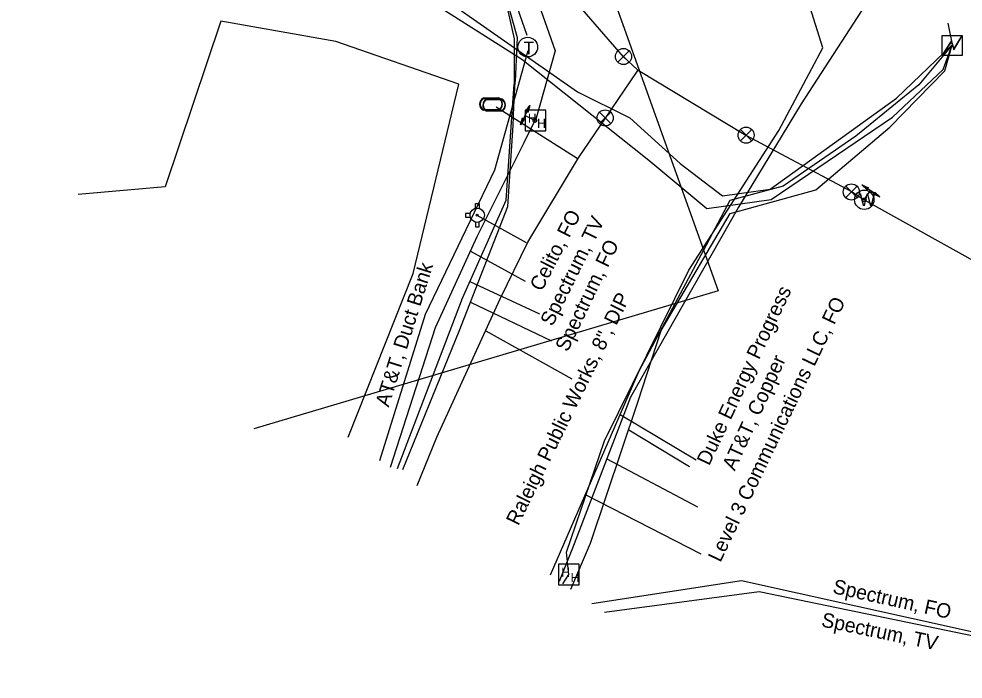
# Model space of a CAD drawing. Extents: x 2070721 to 2083340, y 729290 to 737883.
# Drawn here: x 2080186.1 to 2080447.3, y 733834.7 to 734017.2 of the extents above; entities that cross this region are included whole.
import ezdxf

# ---------------------------------------------------------------- set-up
doc = ezdxf.new("R2010")
doc.units = 0
for name, color, linetype in [('Exist Utilities Power Transformer CELL', 7, 'Continuous'), ('Exist Utilities Power UG Cable SUE LOS B', 7, 'Continuous'), ('Exist Utilities Power UG Cable SUE LOS B Leader', 7, 'Continuous'), ('Exist Utilities Power UG Cable SUE LOS B Text', 7, 'Continuous'), ('Exist Utilities Power UG Cable SUE LOS C', 7, 'Continuous'), ('Exist Utilities Telephone Change of Service SUE CELL', 7, 'Continuous'), ('Exist Utilities Telephone Hand Hole CELL', 7, 'Continuous'), ('Exist Utilities Telephone Manhole CELL', 7, 'Continuous'), ('Exist Utilities Telephone UG Cable SUE LOS C', 7, 'Continuous'), ('Exist Utilities Telephone UG Cable SUE LOS C Leader', 7, 'Continuous'), ('Exist Utilities Telephone UG Cable SUE LOS C Text', 7, 'Continuous'), ('Exist Utilities Telephone UG Conduit SUE LOS B', 7, 'Continuous'), ('Exist Utilities Telephone UG Conduit SUE LOS B Text', 7, 'Continuous'), ('Exist Utilities Telephone UG FO SUE LOS B', 7, 'Continuous'), ('Exist Utilities Telephone UG FO SUE LOS B Leader', 7, 'Continuous'), ('Exist Utilities Telephone UG FO SUE LOS B Text', 7, 'Continuous'), ('Exist Utilities Telephone UG FO SUE LOS C', 7, 'Continuous'), ('Exist Utilities Telephone UG FO SUE LOS C Leader', 7, 'Continuous'), ('Exist Utilities Telephone UG FO SUE LOS C Text', 7, 'Continuous'), ('Exist Utilities TV Hand Hole CELL', 7, 'Continuous'), ('Exist Utilities TV UG Cable SUE LOS C', 7, 'Continuous'), ('Exist Utilities TV UG Cable SUE LOS C Leader', 7, 'Continuous'), ('Exist Utilities TV UG Cable SUE LOS C Text', 7, 'Continuous'), ('Exist Utilities TV UG FO Cable SUE LOS C', 7, 'Continuous'), ('Exist Utilities TV UG FO Cable SUE LOS C Leader', 7, 'Continuous'), ('Exist Utilities TV UG FO Cable SUE LOS C Text', 7, 'Continuous'), ('Exist Utilities Water Change of Service SUE CELL', 7, 'Continuous'), ('Exist Utilities Water Fire Hydrant CELL', 7, 'Continuous'), ('Exist Utilities Water Manhole CELL', 7, 'Continuous'), ('Exist Utilities Water Meter CELL', 7, 'Continuous'), ('Exist Utilities Water UG Line SUE LOS B', 7, 'Continuous'), ('Exist Utilities Water UG Line SUE LOS B Leader', 7, 'Continuous'), ('Exist Utilities Water UG Line SUE LOS B Text', 7, 'Continuous'), ('Exist Utilities Water UG Line SUE LOS C', 7, 'Continuous'), ('Exist Utilities Water Valve CELL', 7, 'Continuous')]:
    doc.layers.add(name, color=color, linetype=linetype)

msp = doc.modelspace()

# ---------------------------------------------------------------- linework, layer by layer
at = {"layer": 'Exist Utilities Power Transformer CELL'}
msp.add_line((2080444.29, 734010.08), (2080444.29, 734010.08), dxfattribs=at)
msp.add_lwpolyline([(2080441.45, 734012.69), (2080447, 734012.69), (2080447, 734007.14), (2080441.45, 734007.14)], close=True, dxfattribs=at)
for points in [[(2080441.45, 734007.14), (2080444.09, 734011.08), (2080444.72, 734008.87), (2080447, 734012.69)], [(2080441.52, 734007.14), (2080444.09, 734010.87), (2080444.68, 734008.69), (2080447, 734012.54)]]:
    msp.add_lwpolyline(points, dxfattribs=at)
at = {"layer": 'Exist Utilities Power UG Cable SUE LOS B'}
msp.add_line((2080444.31, 734010.16), (2080443.13, 734016.08), dxfattribs=at)
for points in [[(2080234.72, 734179.83), (2080241.98, 734171.12), (2080276.22, 734068.16), (2080293.76, 734026.09), (2080325.21, 734006.15), (2080360.35, 733978.15), (2080376.41, 733964.84), (2080394.21, 733967.31), (2080427.72, 733990.11), (2080441.72, 734003.26), (2080444.29, 734010.08)], [(2080338.76, 733859.49), (2080344.21, 733872.23), (2080357.27, 733911.24), (2080363.71, 733931.11), (2080382.81, 733963.43), (2080406.57, 733970.01), (2080426.99, 733987.33), (2080442.22, 734002.87), (2080444.29, 734010.08)]]:
    msp.add_lwpolyline(points, dxfattribs=at)
at = {"layer": 'Exist Utilities Power UG Cable SUE LOS B Leader'}
for p, q in [((2080352.43, 733907.84), (2080373.45, 733895.3)), ((2080354.76, 733903.61), (2080371.56, 733893.48))]:
    msp.add_line(p, q, dxfattribs=at)
at = {"layer": 'Exist Utilities Power UG Cable SUE LOS C'}
for points in [[(2080186.05, 734475.29), (2080232.86, 734351.65), (2080379.47, 733942.04), (2080251.03, 733903.89)], [(2080225.45, 734168.4), (2080244.65, 734158.51), (2080253.95, 734130.69), (2080282.75, 734048.52), (2080295.34, 734028.75), (2080340.63, 733997.06), (2080355.06, 733989.84), (2080368.99, 733977.25), (2080380.73, 733968.31), (2080393.86, 733970.13), (2080428.86, 733995.36), (2080444.29, 734010.08)], [(2080277.17, 733901.6), (2080295.11, 733946.83), (2080307.81, 733999.15), (2080273.72, 734011.03), (2080241.89, 734016.58), (2080226.56, 733970.78), (2080202.47, 733968.66)], [(2080444.29, 734010.08), (2080435.02, 733998.98), (2080417.57, 733984.78), (2080397.54, 733970.98), (2080382.77, 733967.05), (2080376.16, 733954.67), (2080357.6, 733919.78), (2080333.03, 733863.36)]]:
    msp.add_lwpolyline(points, dxfattribs=at)
at = {"layer": 'Exist Utilities Telephone Change of Service SUE CELL'}
for p, q in [((2080327.45, 733993.31), (2080324.79, 733987.98)), ((2080326.05, 733990.51), (2080327.45, 733993.31)), ((2080328.81, 733989.13), (2080326.05, 733990.51)), ((2080328.81, 733989.13), (2080328.81, 733989.13))]:
    msp.add_line(p, q, dxfattribs=at)
for points in [[(2080327.45, 733993.31), (2080326.88, 733991.4), (2080326.76, 733991.93), (2080326.31, 733991.72)], [(2080324.79, 733987.98), (2080325.36, 733989.9), (2080325.48, 733989.37), (2080325.92, 733989.57)]]:
    msp.add_lwpolyline(points, close=True, dxfattribs=at)
msp.add_circle((2080328.81, 733989.13), 0.517, dxfattribs=at)
at = {"layer": 'Exist Utilities Telephone Hand Hole CELL'}
for p, q in [((2080326.08, 733992.03), (2080326.08, 733986.31)), ((2080331.8, 733992.03), (2080326.08, 733992.03)), ((2080331.8, 733986.31), (2080331.8, 733992.03)), ((2080328.94, 733989.17), (2080328.94, 733989.17)), ((2080326.08, 733986.31), (2080331.8, 733986.31))]:
    msp.add_line(p, q, dxfattribs=at)
at = {"layer": 'Exist Utilities Telephone Manhole CELL'}
msp.add_circle((2080326.85, 734009.45), 2.72, dxfattribs=at)
at = {"layer": 'Exist Utilities Telephone UG Cable SUE LOS C'}
for points in [[(2080294.22, 734238.68), (2080294.22, 734221.46), (2080303.86, 734176.45), (2080326.14, 734123.68), (2080343.11, 734086.02), (2080369.71, 734062.6), (2080410.57, 734039.8), (2080423.78, 734028.65), (2080421.38, 734022.96), (2080402.46, 733993.71), (2080385.13, 733965.19), (2080355.27, 733912.59), (2080339.2, 733870.84), (2080335.53, 733861.67)], [(2080326.66, 734012.62), (2080321.93, 734026.22), (2080291.1, 734070.12)]]:
    msp.add_lwpolyline(points, dxfattribs=at)
at = {"layer": 'Exist Utilities Telephone UG Cable SUE LOS C Leader'}
msp.add_line((2080348.73, 733895.58), (2080373.8, 733882.27), dxfattribs=at)
at = {"layer": 'Exist Utilities Telephone UG Conduit SUE LOS B'}
msp.add_lwpolyline([(2080285.9, 733895.15), (2080298.57, 733935.59), (2080317.74, 733975.49), (2080326.94, 734008.53)], dxfattribs=at)
at = {"layer": 'Exist Utilities Telephone UG FO SUE LOS B'}
msp.add_lwpolyline([(2080328.81, 733989.13), (2080325.75, 733983.01), (2080312.77, 733957.01), (2080301.25, 733931.83), (2080288.79, 733893.2)], dxfattribs=at)
at = {"layer": 'Exist Utilities Telephone UG FO SUE LOS B Leader'}
msp.add_line((2080310.98, 733953.01), (2080326.08, 733944.75), dxfattribs=at)
at = {"layer": 'Exist Utilities Telephone UG FO SUE LOS C'}
for points in [[(2080285.47, 734081.3), (2080286.04, 734080.39), (2080313.44, 734043.19), (2080329.21, 734023.2), (2080334.41, 734008.43), (2080328.94, 733989.17)], [(2080336.57, 733860.97), (2080338.22, 733863.58), (2080337.51, 733869.77), (2080348.05, 733900.55), (2080371.36, 733947.72), (2080396.33, 733986.42), (2080408.45, 734009.24), (2080401.96, 734030.18)]]:
    msp.add_lwpolyline(points, dxfattribs=at)
at = {"layer": 'Exist Utilities Telephone UG FO SUE LOS C Leader'}
msp.add_line((2080342.93, 733885.6), (2080374.73, 733869.31), dxfattribs=at)
at = {"layer": 'Exist Utilities TV Hand Hole CELL'}
msp.add_line((2080338.22, 733863.58), (2080338.22, 733863.58), dxfattribs=at)
msp.add_lwpolyline([(2080335.34, 733860.7), (2080341.09, 733860.7), (2080341.09, 733866.45), (2080335.34, 733866.45), (2080335.34, 733860.7)], dxfattribs=at)
at = {"layer": 'Exist Utilities TV UG Cable SUE LOS C'}
for points in [[(2080320.73, 734021.92), (2080323.11, 734011.73), (2080323.11, 733999.23)], [(2080290.82, 733892.89), (2080308.74, 733940.03), (2080320.87, 733967.1), (2080322.56, 733991.38), (2080323.11, 733999.23)], [(2080348.09, 733853.2), (2080390.88, 733858.86), (2080496.55, 733837.03), (2080500.76, 733835.64), (2080507.3, 733832.49), (2080516.48, 733827.67), (2080540.8, 733815.65), (2080567.67, 733802.85), (2080580.43, 733797.42), (2080591.34, 733793.44), (2080601.46, 733789.48)]]:
    msp.add_lwpolyline(points, dxfattribs=at)
at = {"layer": 'Exist Utilities TV UG Cable SUE LOS C Leader'}
msp.add_line((2080310.81, 733944.61), (2080330.1, 733935.71), dxfattribs=at)
at = {"layer": 'Exist Utilities TV UG FO Cable SUE LOS C'}
for points in [[(2080321.01, 734022.31), (2080323.92, 734012.13), (2080323.35, 733999.94)], [(2080292.27, 733892.65), (2080307.82, 733930.84), (2080321.29, 733965.32), (2080322.78, 733987.76), (2080323.02, 733992.9), (2080323.35, 733999.94)], [(2080344.57, 733855.58), (2080386, 733861.95), (2080496.25, 733837.52)]]:
    msp.add_lwpolyline(points, dxfattribs=at)
at = {"layer": 'Exist Utilities TV UG FO Cable SUE LOS C Leader'}
msp.add_line((2080310.99, 733938.88), (2080333.44, 733928.18), dxfattribs=at)
at = {"layer": 'Exist Utilities Water Change of Service SUE CELL'}
for p, q in [((2080424.25, 733968), (2080419.3, 733971.32)), ((2080419.93, 733967.18), (2080421.65, 733969.74)), ((2080421.65, 733969.74), (2080424.25, 733968)), ((2080419.93, 733967.18), (2080419.93, 733967.18))]:
    msp.add_line(p, q, dxfattribs=at)
for points in [[(2080419.3, 733971.32), (2080421.13, 733970.5), (2080420.59, 733970.45), (2080420.74, 733969.99)], [(2080424.25, 733968), (2080422.42, 733968.81), (2080422.96, 733968.86), (2080422.82, 733969.33)]]:
    msp.add_lwpolyline(points, close=True, dxfattribs=at)
msp.add_circle((2080419.93, 733967.18), 0.517, dxfattribs=at)
at = {"layer": 'Exist Utilities Water Fire Hydrant CELL'}
msp.add_line((2080312.85, 733962.96), (2080312.85, 733962.96), dxfattribs=at)
for points in [[(2080312.34, 733964.87), (2080312.34, 733966.16), (2080313.36, 733966.16), (2080313.36, 733964.85)], [(2080310.94, 733963.47), (2080309.65, 733963.47), (2080309.65, 733962.45), (2080310.94, 733962.45)], [(2080312.34, 733961.05), (2080312.34, 733959.76), (2080313.36, 733959.76), (2080313.36, 733961.07)]]:
    msp.add_lwpolyline(points, dxfattribs=at)
for radius in [1.98, 0.243]:
    msp.add_circle((2080312.85, 733962.96), radius, dxfattribs=at)
at = {"layer": 'Exist Utilities Water Manhole CELL'}
msp.add_line((2080419.93, 733967.21), (2080419.93, 733967.21), dxfattribs=at)
msp.add_circle((2080419.93, 733967.22), 2.69, dxfattribs=at)
at = {"layer": 'Exist Utilities Water Meter CELL'}
for p, q in [((2080316.68, 733993.7), (2080316.68, 733993.7)), ((2080317.54, 733993.42), (2080317.54, 733993.42))]:
    msp.add_line(p, q, dxfattribs=at)
for points in [[(2080314.64, 733995.4), (2080318.72, 733995.4)], [(2080314.64, 733995.26), (2080318.72, 733995.26)], [(2080315.5, 733995.12), (2080319.58, 733995.12)], [(2080315.5, 733994.98), (2080319.58, 733994.98)], [(2080318.72, 733992.14), (2080314.62, 733992.14)], [(2080318.72, 733992), (2080314.62, 733992)], [(2080319.58, 733991.86), (2080315.48, 733991.86)], [(2080319.58, 733991.72), (2080315.48, 733991.72)]]:
    msp.add_lwpolyline(points, dxfattribs=at)
for centre, radius, start, end in [((2080315.37, 733993.69), 1.86, 113.178, 245.9794), ((2080315.38, 733993.69), 1.73, 115.3009, 243.7824), ((2080316.23, 733993.41), 1.86, 113.178, 245.9794), ((2080316.24, 733993.41), 1.73, 115.3009, 243.7824), ((2080317.97, 733993.7), 1.86, 293.6483, 66.3084), ((2080317.98, 733993.7), 1.73, 295.1272, 64.8728), ((2080318.83, 733993.42), 1.86, 293.6483, 66.3084), ((2080318.84, 733993.42), 1.73, 295.1272, 64.8728)]:
    msp.add_arc(centre, radius, start, end, dxfattribs=at)
at = {"layer": 'Exist Utilities Water UG Line SUE LOS B'}
for p, q in [((2080340.5, 733978.59), (2080318.05, 733992.79)), ((2080326.49, 733955.32), (2080312.83, 733962.88))]:
    msp.add_line(p, q, dxfattribs=at)
for points in [[(2080357.06, 734003.27), (2080353.32, 734006.79), (2080296.63, 734072.2), (2080261.95, 734141.13), (2080251.22, 734185.42), (2080250, 734189.2), (2080244.12, 734248.6), (2080244.13, 734251.5), (2080244.63, 734259.68), (2080245.13, 734264.1), (2080254.44, 734320.44), (2080276.53, 734380.91), (2080391.41, 734503.18), (2080497.9, 734548.7), (2080500.72, 734549.83), (2080585.45, 734578.7), (2080702.53, 734619.89), (2080710.17, 734622.62), (2080743.51, 734634.52), (2080754.26, 734638.28), (2080902.52, 734692.58), (2081024.44, 734735.33)], [(2080296.23, 733888.18), (2080301.7, 733901.61), (2080319.24, 733939.81), (2080326.85, 733955.51), (2080340.87, 733978.79), (2080348.3, 733989.77), (2080357.09, 734002.68), (2080357.34, 734003.04)], [(2080357.06, 734003.27), (2080357.34, 734003.04), (2080387.17, 733985.06), (2080416.62, 733969.4), (2080419.93, 733967.18)]]:
    msp.add_lwpolyline(points, dxfattribs=at)
at = {"layer": 'Exist Utilities Water UG Line SUE LOS B Leader'}
msp.add_line((2080315.22, 733930.94), (2080339.02, 733917.7), dxfattribs=at)
at = {"layer": 'Exist Utilities Water UG Line SUE LOS C'}
msp.add_lwpolyline([(2080419.93, 733967.18), (2080512.22, 733915.86), (2080684.81, 733822.52), (2080926.94, 733749.77), (2081207.6, 733698.37)], dxfattribs=at)
at = {"layer": 'Exist Utilities Water Valve CELL'}
for points in [[(2080354.9, 734008.41), (2080351.75, 734005.26), (2080353.32, 734006.83), (2080354.9, 734005.26), (2080351.75, 734008.41)], [(2080349.82, 733991.44), (2080346.68, 733988.29), (2080348.25, 733989.86), (2080349.82, 733988.29), (2080346.68, 733991.44)], [(2080388.81, 733986.67), (2080385.67, 733983.52), (2080387.24, 733985.09), (2080388.81, 733983.52), (2080385.67, 733986.67)], [(2080417.94, 733970.95), (2080414.79, 733967.81), (2080416.36, 733969.38), (2080417.94, 733967.81), (2080414.79, 733970.95)]]:
    msp.add_lwpolyline(points, dxfattribs=at)
for centre in [(2080353.32, 734006.83), (2080348.25, 733989.86), (2080387.24, 733985.09), (2080416.36, 733969.38)]:
    msp.add_circle(centre, 2.23, dxfattribs=at)

# ---------------------------------------------------------------- texts
at = {"layer": 'Exist Utilities Power UG Cable SUE LOS B Text'}
msp.add_text('Duke Energy Progress', height=4, rotation=64.8519, dxfattribs=at).set_placement((2080377.02, 733893.48))
at = {"layer": 'Exist Utilities Telephone Hand Hole CELL'}
for p in [(2080326.86, 733988.58), (2080329.43, 733987.11)]:
    msp.add_text('H', height=2.5, dxfattribs=at).set_placement(p)
at = {"layer": 'Exist Utilities Telephone Manhole CELL'}
msp.add_text('T', height=3.5, dxfattribs=at).set_placement((2080325.68, 734007.44))
at = {"layer": 'Exist Utilities Telephone UG Cable SUE LOS C Text'}
msp.add_text('AT&T, Copper', height=4, rotation=65.3806, dxfattribs=at).set_placement((2080384.1, 733892.04))
at = {"layer": 'Exist Utilities Telephone UG Conduit SUE LOS B Text'}
msp.add_text('AT&T, Duct Bank', height=4, rotation=72.6064, dxfattribs=at).set_placement((2080288.36, 733909.7))
at = {"layer": 'Exist Utilities Telephone UG FO SUE LOS B Text'}
msp.add_text('Celito, FO ', height=4, rotation=63.0173, dxfattribs=at).set_placement((2080330.74, 733941.66))
at = {"layer": 'Exist Utilities Telephone UG FO SUE LOS C Text'}
msp.add_text('Level 3 Communications LLC, FO', height=4, rotation=64.369, dxfattribs=at).set_placement((2080380.12, 733866.75))
at = {"layer": 'Exist Utilities TV Hand Hole CELL'}
for p in [(2080336.13, 733862.93), (2080338.7, 733861.47)]:
    msp.add_text('H', height=2.5, dxfattribs=at).set_placement(p)
at = {"layer": 'Exist Utilities TV UG Cable SUE LOS C Text'}
for s, rotation, p in [('Spectrum, TV ', 63.7218, (2080333.68, 733932.01)), ('Spectrum, TV', 348.3287, (2080407.84, 733849.23))]:
    msp.add_text(s, height=4, rotation=rotation, dxfattribs=at).set_placement(p)
at = {"layer": 'Exist Utilities TV UG FO Cable SUE LOS C Text'}
for s, rotation, p in [('Spectrum, FO ', 64.5306, (2080337.86, 733924.92)), ('Spectrum, FO', 347.5069, (2080410.99, 733858.46))]:
    msp.add_text(s, height=4, rotation=rotation, dxfattribs=at).set_placement(p)
at = {"layer": 'Exist Utilities Water Manhole CELL'}
msp.add_text('W', height=3.5, dxfattribs=at).set_placement((2080418.58, 733965.46))
at = {"layer": 'Exist Utilities Water UG Line SUE LOS B Text'}
msp.add_text('Raleigh Public Works, 8", DIP ', height=4, rotation=63.943, dxfattribs=at).set_placement((2080324.23, 733876.88))

doc.saveas('drawing.dxf')
